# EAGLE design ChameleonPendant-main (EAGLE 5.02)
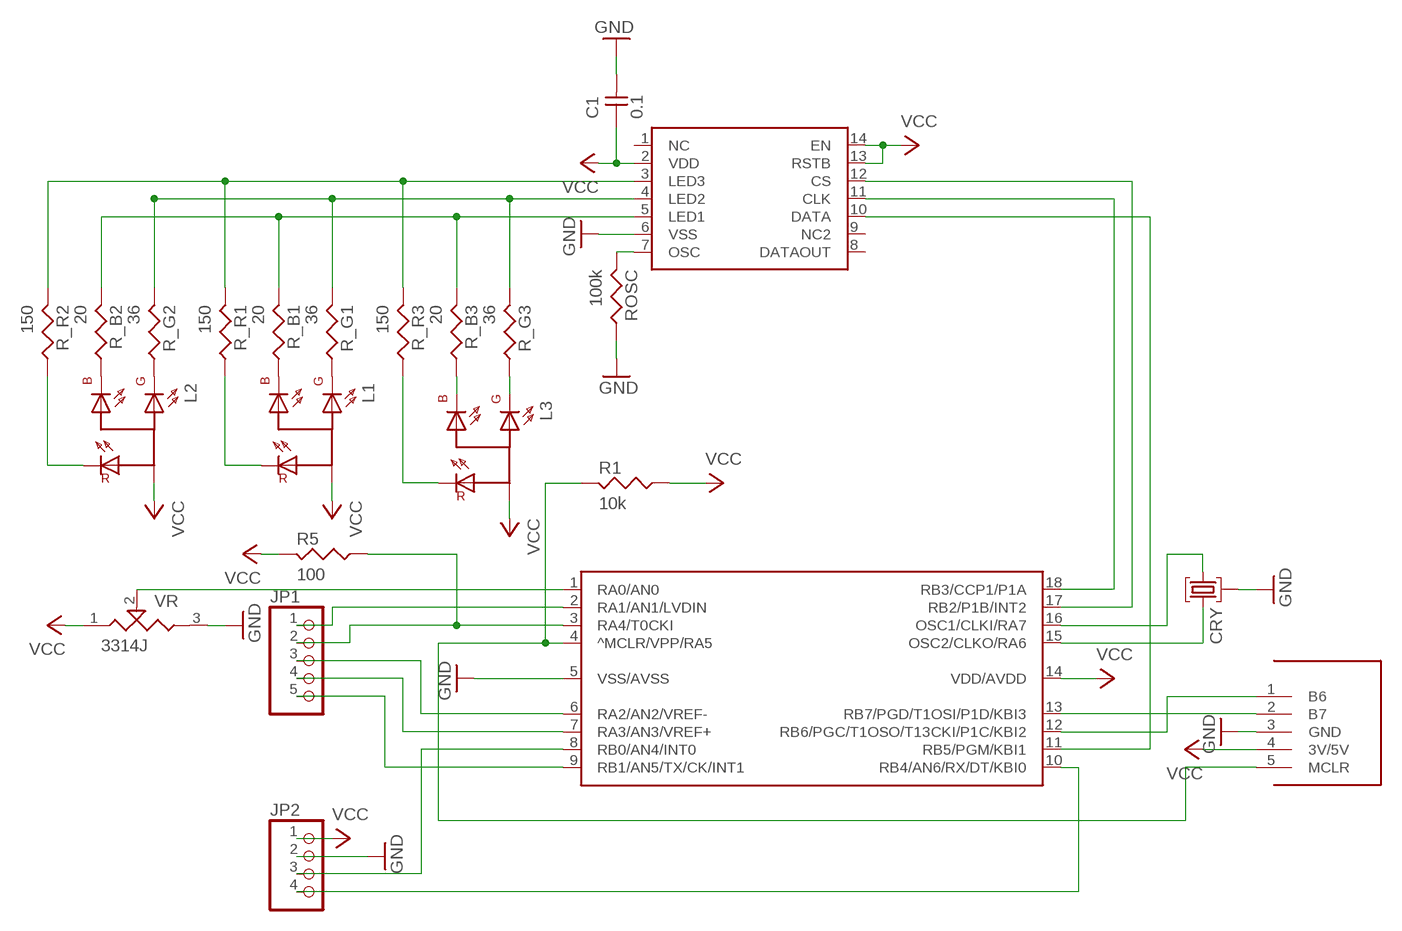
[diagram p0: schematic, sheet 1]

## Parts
C1  0.1  1608  [1608]
CRY  3-PIN-CRYSTALFLAT20M  [CRYSTAL-FLAT-20M]
JP1  PINHD-1X5DIP  [1X05]
JP2  PINHD-1X4DIP  [1X04]
L1  FULL_CHIPLED(LATBT66B)  [LATBT66B]
L2  FULL_CHIPLED(LATBT66B)  [LATBT66B]
L3  FULL_CHIPLED(LATBT66B)  [LATBT66B]
R1  10k  1608  [1608]
R5  100  1608  [1608]
R_B1  20  1608  [1608]
R_B2  20  1608  [1608]
R_B3  20  1608  [1608]
R_G1  36  1608  [1608]
R_G2  36  1608  [1608]
R_G3  36  1608  [1608]
R_R1  150  1608  [1608]
R_R2  150  1608  [1608]
R_R3  150  1608  [1608]
ROSC  100k  1608  [1608]
U$1  PIC18F1220SO  [SO-18W]
U$3  MODULAR-MINI08  [1.5MM-1X5S-8MM]
U$4  NJU6061  [SSOP14]
VR  3314J  [3314J]

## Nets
GND: C1.P$2 CRY.G(GND) JP2.2 ROSC.1 U$1.5(VSS/AVSS) U$3.3(GND) U$4.6(VSS) VR.3
N$1: R1.2 U$1.4(^MCLR/VPP/RA5) U$3.5(MCLR)
N$2: ROSC.2 U$4.7(OSC)
N$3: R_R1.2 R_R2.2 R_R3.2 U$4.3(LED3)
N$4: R_G1.2 R_G2.2 R_G3.2 U$4.4(LED2)
N$5: R_B1.2 R_B2.2 R_B3.2 U$4.5(LED1)
N$6: U$1.12(RB6/PGC/T1OSO/T13CKI/P1C/KBI2) U$3.1(B6)
N$7: L1.1(RED_C) R_R1.1
N$8: L3.1(RED_C) R_R3.1
N$9: L3.3(BLUE_C) R_B3.1
N$10: L3.4(GREEN_C) R_G3.1
N$11: L1.3(BLUE_C) R_B1.1
N$12: U$1.11(RB5/PGM/KBI1) U$4.10(DATA)
N$13: U$1.17(RB2/P1B/INT2) U$4.12(CS)
N$14: U$1.18(RB3/CCP1/P1A) U$4.11(CLK)
N$15: U$1.13(RB7/PGD/T1OSI/P1D/KBI3) U$3.2(B7)
N$16: CRY.O2 U$1.15(OSC2/CLKO/RA6)
N$17: CRY.O1 U$1.16(OSC1/CLKI/RA7)
N$18: U$1.1(RA0/AN0) VR.2
N$19: JP2.3 U$1.8(RB0/AN4/INT0)
N$20: L1.4(GREEN_C) R_G1.1
N$21: JP2.4 U$1.10(RB4/AN6/RX/DT/KBI0)
N$22: L2.1(RED_C) R_R2.1
N$23: L2.3(BLUE_C) R_B2.1
N$24: L2.4(GREEN_C) R_G2.1
N$25: JP1.1 U$1.2(RA1/AN1/LVDIN)
N$26: JP1.2 R5.1 U$1.3(RA4/T0CKI)
N$27: JP1.3 U$1.6(RA2/AN2/VREF-)
N$28: JP1.4 U$1.7(RA3/AN3/VREF+)
N$29: JP1.5 U$1.9(RB1/AN5/TX/CK/INT1)
VCC: C1.P$1 JP2.1 L1.2(A) L2.2(A) L3.2(A) R1.1 R5.2 U$1.14(VDD/AVDD) U$3.4(3V/5V) U$4.2(VDD) U$4.13(RSTB) U$4.14(EN) VR.1
Unconnected: U$4.1(NC) U$4.8(DATAOUT) U$4.9(NC2)

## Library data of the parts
C1 = 01_capacitor:1608
CRY = 00_other-parts:3-PIN-CRYSTAL: 3-pin crystal (center ground)
JP1 = 09_con-pin:PINHD-1X5: PIN HEADER
JP2 = 09_con-pin:PINHD-1X4: PIN HEADER
L1-L3 = 06_led:FULL_CHIPLED(LATBT66B)
R1 R5 R_B1-R_B3 R_G1-R_G3 R_R1-R_R3 ROSC = 02_resistor:1608
U$1 = 12_pic-micro:PIC18F1220
U$3 = 00_other-parts:MODULAR-MINI
U$4 = 10_other-ic:NJU6061
VR = 02_resistor:3314J

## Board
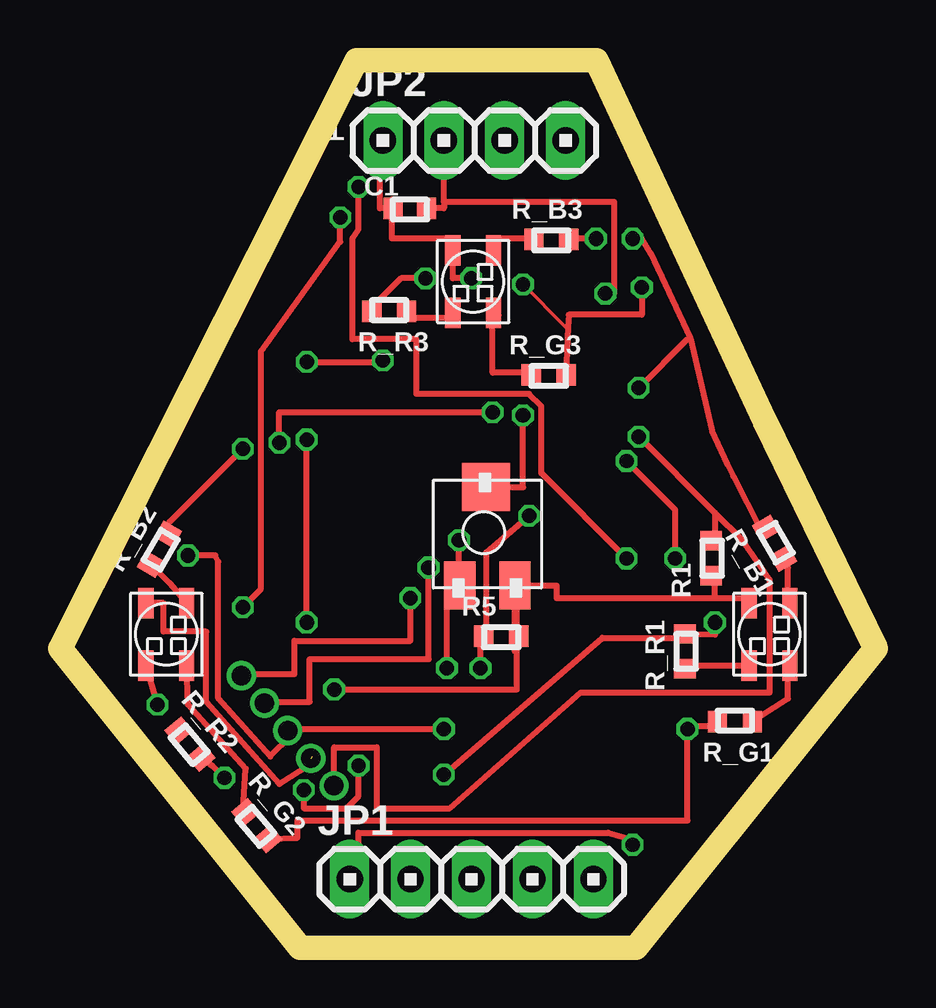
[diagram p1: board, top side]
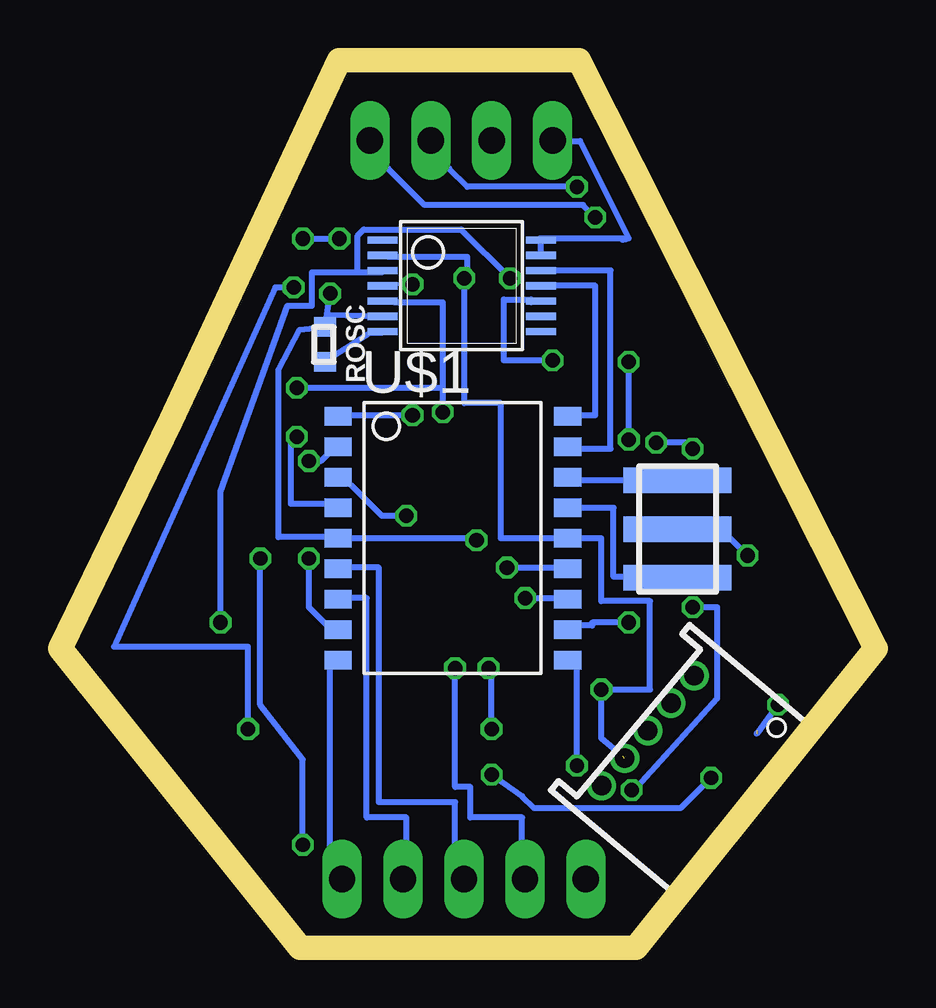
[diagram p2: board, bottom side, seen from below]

Size 34 x 37 mm. Coordinates in mm from the lower left corner, seen from the top.
Outline: 29.37,22 22.37,37 12.37,37 0,12.47 10,0 24,0 34,12.47 29.37,22
Copper layers (1*16): Top 0.035mm / dielectric 1.5mm / Bottom 0.035mm
Design rules "p-ban_min": minimum track width 0.15mm, minimum drill 0.3mm, track to track 0.15mm, track to pad 0.15mm, pad to pad 0.15mm, via to via 0.15mm, smd to smd 0.15mm, copper to edge 0.7mm, drill to drill 0.45mm, minimum pad ring 0.15mm, minimum via ring 0.15mm, stop-mask expansion 4mil, vias tented up to drill 0mil, thermal gap 0.15mm

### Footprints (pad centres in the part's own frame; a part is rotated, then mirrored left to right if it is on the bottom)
1608 = smd 0.8 x 0.9: P$1 -0.7,0.1; P$2 0.7,0.1
CRYSTAL-FLAT-20M = smd 1.067 x 4.5: G 0.027,0.016; O1 -2.019,0.016; O2 2.046,0.016
1X05 = drill 1.092 long: 1 -5.08,0; 2 -2.54,0; 3 0,0; 4 2.54,0; 5 5.08,0
1X04 = drill 1.092 long: 1 -3.81,0; 2 -1.27,0; 3 1.27,0; 4 3.81,0
LATBT66B = smd 0.635 x 1.27: 1 -0.85,-1.3; 2 -0.85,1.3; 3 0.85,1.3; 4 0.85,-1.3
1608' = smd 0.8 x 0.9: 1 -0.715,0.037; 2 0.739,0.037
SO-18W = smd 0.762 x 1.143: 1 -5.08,-4.788; 2 -3.81,-4.788; 3 -2.54,-4.788; 4 -1.27,-4.788; 5 0,-4.788; 6 1.27,-4.788; 7 2.54,-4.788; 8 3.81,-4.788; 9 5.08,-4.788; 10 5.08,4.788; 11 3.81,4.788; 12 2.54,4.788; 13 1.27,4.788; 14 0,4.788; 15 -1.27,4.788; 16 -2.54,4.788; 17 -3.81,4.788; 18 -5.08,4.788
1.5MM-1X5S-8MM = drill 0.813 round: 1 -3,-2; 2 -1.5,-2; 3 0,-2; 4 1.5,-2; 5 3,-2
SSOP14 = smd 0.305 x 1.245: 1 -1.587,-3.302; 2 -0.952,-3.302; 3 -0.317,-3.302; 4 0.318,-3.302; 5 0.953,-3.302; 6 1.588,-3.302; 7 2.223,-3.302; 8 2.223,3.302; 9 1.588,3.302; 10 0.953,3.302; 11 0.318,3.302; 12 -0.317,3.302; 13 -0.952,3.302; 14 -1.587,3.302
3314J = smd 1.3 x 2: 1 1.4,-2.4; 3 -0.9,-2.4 | smd 2 x 2: 2 0.2,1.7

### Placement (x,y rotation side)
C1  14.59,30.72 0 top
CRY  8.27,17.46 270 bottom
JP1  17.16,2.85 0 top
JP2  17.27,33.64 0 top
L1  29.58,13.06 0 top
L2  4.44,13.06 0 top
L3  17.22,27.76 0 top
R1  10k  [1608']  27.18,16.22 90 top
R5  100  [1608']  18.39,12.95 0 top
R_B1  20  [1608']  29.83,16.86 120 top
R_B2  20  [1608']  4.18,16.58 60 top
R_B3  20  [1608']  20.47,29.49 0 top
R_G1  36  [1608']  28.15,9.45 180 top
R_G2  36  [1608']  8.17,5.07 310 top
R_G3  36  [1608']  20.36,23.84 0 top
R_R1  150  [1608']  26.09,12.34 90 top
R_R2  150  [1608']  5.39,8.47 310 top
R_R3  150  [1608']  13.73,26.56 180 top
ROSC  100k  [1608']  22.99,25.16 270 bottom
U$1  17.62,17.06 270 bottom
U$3  7.96,7.75 230 bottom
U$4  17.25,27.9 270 bottom
VR  17.57,17.49 0 top

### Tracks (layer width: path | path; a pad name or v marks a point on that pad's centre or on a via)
GND  (via drill 0.61)
  Top 0.254: JP2.2 16,31.08 | C1.P$2 16,30.82 16,31.08 | v5.33,16.34 6.48,16.34 6.6,16.09 6.6,10.38 8.76,7.96 9.65,8.85 | 9.65,8.85 9.91,9.11 | 16.67,15.04 VR.3 | 16.67,15.04 16.76,14.95 16.64,14.95 | 16,31.08 23.11,31.08 23.11,27.27 v22.73,27.27 | 16.64,14.95 16.64,14.57 | 16.64,14.95 v16.64,16.98 | 16.67,15.04 16.13,15.04 v16.13,11.65 | 9.65,9.11 v16,9.11 | 9.65,8.85 9.65,9.11 | 9.4,9.11 9.4,9.04 U$3.3 | 9.65,9.11 9.4,9.11 | 9.4,9.11 9.4,9.23
  Bottom 0.254: 22.86,26.38 ROSC.1 24,25.76 24.89,24.09 24.89,17.11 22.35,17.11 22.35,17.06 U$1.5 16.64,17.06 v16.64,16.98 | 22.86,26.38 U$4.6 | 7.62,17.11 7.95,17.43 CRY.G 6.42,17.43 v5.33,16.34 | 22.86,26.38 v22.73,27.27 | v16.13,11.65 16,11.65 v16,9.11
N$1  (via drill 0.6)
  Top 0.254: 27.3,18.12 28.45,16.98 29.59,15.33 29.59,10.63 21.72,10.63 16.26,5.8 13.21,5.8 13.21,8.34 11.43,8.34 U$3.5 | 27.3,18.12 v24.13,21.3 | U$3.5 11.43,6.57 | U$3.5 | R1.2 27.3,16.96 27.3,18.12
  Bottom 0.15: v24.13,21.3 24.38,21.3 | 22.86,18.5 U$1.4
  Bottom 0.254: 22.86,18.5 24.38,18.5 24.38,21.3
N$2
  Bottom 0.254: ROSC.2 21.08,25.62 20.57,25.62 U$4.7
N$3  (via drill 0.6, 0.61)
  Top 0.15: 25.65,12.92 R_R1.2 | 13.21,26.89 R_R3.2
  Top 0.254: R_R1.2 27.3,13.04 v27.3,13.55 | v6.86,7.07 6.35,7.58 R_R2.2 | v16,7.2 22.61,12.92 25.65,12.92 | 13.21,26.89 14.22,27.9 v15.24,27.9
  Bottom 0.254: v27.3,13.55 27.3,19.01 24.51,26.76 23.5,26.76 23.5,28.16 21.59,28.16 | U$4.3 20.57,28.16 21.59,28.16 | v6.86,7.07 8.13,5.8 14.22,5.8 14.73,6.31 v16,7.2 | v15.24,27.9 17.27,29.93 21.34,29.93 21.59,29.68 21.59,28.16
N$4  (via drill 0.6, 0.61)
  Top 0.15: v19.3,27.65 21.08,25.87 21.18,25.87
  Top 0.254: R_G2.2 9.91,4.58 9.91,5.3 26.16,5.3 v26.16,9.11 26.16,9.23 27.43,9.23 27.43,9.35 | 27.43,9.35 27.43,9.36 | 27.43,9.35 R_G1.2 | v24.26,27.52 24.26,26.38 21.21,26.38 21.18,25.87 R_G3.2
  Bottom 0.15: v19.3,27.65 20.07,27.65 U$4.4
  Bottom 0.254: v26.16,9.11 26.16,12.54 31.75,12.54 25.02,27.52 v24.26,27.52
N$5  (via drill 0.6, 0.61)
  Top 0.15: R_B2.2 4.57,17.74 | 26.16,25.36 26.28,25.41
  Top 0.254: R_B1.2 29.21,17.4 28.07,19.65 27.81,20.15 27.18,21.55 26.28,25.41 24.64,28.92 24.26,29.55 v23.88,29.55 | 21.34,29.55 R_B3.2 | v22.35,29.55 21.34,29.55 | 21.34,29.55 21.34,29.43 | 4.57,17.74 v7.62,20.79 | v9.14,21.04 9.14,22.31 v18.03,22.31 | v24.13,23.33 26.16,25.36
  Bottom 0.15: v7.62,20.79 7.87,21.04 | 20.07,26.89 U$4.5
  Bottom 0.254: v23.88,29.55 v22.35,29.55 | 7.87,21.04 v9.14,21.04 | 18.03,23.33 18.03,26.89 20.07,26.89 | v18.03,22.31 18.03,23.33 | 18.03,23.33 v24.13,23.33
N$6  (via drill 0.61)
  Top 0.254: v14.61,14.57 14.61,12.79 9.78,12.79 9.78,11.4 7.62,11.4 7.62,11.34 U$3.1
  Bottom 0.254: U$1.12 12.83,14.44 | U$1.12 | v14.61,14.57 12.83,14.57 U$1.12
N$7
  Top 0.254: 26.04,11.61 26.04,11.52 | R_R1.1 26.04,11.61 | L1.1 26.04,11.76 26.04,11.61
N$8
  Top 0.254: L3.1 16.38,26.25 14.61,26.25 14.61,26.46 | 14.61,26.46 14.61,26.5 | R_R3.1 14.61,26.46
N$9
  Top 0.254: L3.3 18.03,29.06 18.03,29.55 19.81,29.55 19.81,29.59 R_B3.1
N$10
  Top 0.254: 18.29,26.35 18.03,26.46 L3.4 | 18.29,26.35 18.03,26.5 | 18.29,26.35 18.03,26.35 18.03,23.96 19.56,23.96 19.56,23.94 R_G3.1
N$11
  Top 0.254: R_B1.1 30.23,16.07 30.1,15.96 30.35,15.84 30.35,14.36 L1.3
N$12  (via drill 0.6, 0.61)
  Top 0.254: v10.29,13.55 v10.29,21.17 | v10.29,24.41 13.46,24.41 v13.46,24.47
  Bottom 0.254: v10.29,21.17 v10.29,24.41 | v10.29,13.55 11.81,13.55 11.81,13.42 12.95,13.42 12.95,13.25 U$1.11 | v13.46,24.47 15.49,24.47 15.49,27.01 14.35,27.01 14.35,26.95 | 14.35,26.95 14.35,26.89 | 14.35,26.95 U$4.10
N$13
  Bottom 0.254: U$4.12 11.05,28.22 11.05,20.79 12.57,20.79 12.57,20.87 U$1.17
N$14
  Bottom 0.254: U$4.11 11.68,27.58 11.68,22.19 13.08,22.19 13.08,22.14 U$1.18
N$15  (via drill 0.61)
  Top 0.254: 8.89,10.25 | 8.89,10.25 10.41,10.25 10.41,12.03 15.37,12.03 v15.37,15.84 | U$3.2 8.51,10.19 8.51,10.25 8.89,10.25
  Bottom 0.254: U$1.13 12.83,15.84 v15.37,15.84
N$16
  Bottom 0.254: U$1.15 10.92,18.33 10.92,15.46 8.13,15.46 8.13,15.41 | 8.13,15.41 8.13,15.33 | CRY.O2 8.13,15.41
N$17
  Bottom 0.254: 13.08,19.48 13.08,19.6 U$1.16 | CRY.O1 13.08,19.48 | 13.08,19.48 13.08,19.39
N$18  (via drill 0.61)
  Top 0.254: VR.2 19.3,19.19 v19.3,22.19
  Bottom 0.254: 22.48,22.14 22.48,22.06 | 22.48,22.14 U$1.1 | v19.3,22.19 22.48,22.19 22.48,22.14
N$19  (via drill 0.6)
  Top 0.254: v23.62,16.22 20.07,19.77 20.07,22.57 19.56,23.08 14.86,23.08 14.86,25.36 12.19,25.36 12.19,29.55 12.45,29.93 v12.45,31.71
  Bottom 0.15: U$1.8 22.86,13.42
  Bottom 0.254: 22.86,13.42 23.62,14.19 v23.62,16.22 | v12.45,31.71 17.02,31.71 17.78,32.47 JP2.3
N$20
  Top 0.254: L1.4 30.35,12.01 30.35,10.38 28.96,9.49 28.96,9.35 R_G1.1
N$21  (via drill 0.6)
  Top 0.254: v12.45,7.58 12.45,6.31 11.94,5.8 10.16,5.8 v10.16,6.57 | v7.62,14.19 8.38,14.95 8.38,24.85 11.68,29.43 v11.68,30.44
  Bottom 0.15: 10.16,6.44 v10.16,6.57 | 12.45,11.65 U$1.10
  Bottom 0.254: v12.45,7.58 12.45,11.65 | 10.16,6.44 6.6,10.38 6.6,14.19 v7.62,14.19 | v11.68,30.44 12.19,30.95 18.8,30.95 20.32,32.47 JP2.4
N$22  (via drill 0.6)  (1 unrouted)
  Top 0.254: v4.06,10.12 L2.1
  Bottom 0.254: v4.06,10.12 4.95,8.92
N$23
  Top 0.254: R_B2.1 4.57,15.2 L2.3
N$24
  Top 0.254: L2.4 5.33,10.12 7.75,7.46 7.62,5.42 R_G2.1
N$25  (via drill 0.6)
  Top 0.254: v23.62,20.28 25.65,18.25 v25.65,16.22 | v23.88,4.28 23.75,4.28 23.75,4.53 22.86,4.79 12.45,4.79 12.45,4.28 JP1.1
  Bottom 0.15: 22.86,20.54 U$1.2
  Bottom 0.254: 22.86,20.54 23.11,20.28 v23.62,20.28 | v25.65,16.22 25.65,10.12 23.88,7.84 v23.88,4.28
N$26  (via drill 0.6, 0.61)
  Top 0.15: R5.1 17.78,13.42
  Top 0.254: R5.1 17.53,13.05 v17.53,11.65 | v19.56,18 17.78,16.47 17.78,13.42
  Bottom 0.15: 21.84,19.27 U$1.3
  Bottom 0.254: JP1.2 14.73,2.85 14.73,5.42 16.89,5.42 16.89,6.69 17.53,6.69 v17.53,11.65 | 21.84,19.27 20.57,18 v19.56,18
N$27
  Bottom 0.254: JP1.3 17.53,2.85 17.53,6.06 20.7,6.06 20.7,15.84 22.35,15.84 22.35,15.79 U$1.6
N$28
  Bottom 0.254: JP1.4 19.56,2.85 19.56,5.42 21.21,5.42 21.21,14.57 22.23,14.57 | 22.23,14.57 22.23,14.52 U$1.7 | 22.23,14.57 22.23,14.69
N$29
  Bottom 0.254: 22.73,11.98 22.73,12.03 | 22.73,11.98 U$1.9 | JP1.5 22.73,2.85 22.73,11.98
VCC  (via drill 0.61)  (1 unrouted)
  Top 0.254: JP2.1 13.46,33.11 13.34,33.11 13.34,30.82 C1.P$1 13.84,31.2 13.84,29.55 16.26,29.55 16.26,29.17 | 16.26,29.06 16.26,28.92 | 16.26,29.06 L3.2 | 16.26,29.17 16.26,29.06 | R5.2 19.05,12.54 19.05,13.42 | VR.1 19.05,15.09 19.05,13.42 | VR.1 20.7,15.09 20.7,14.57 27.3,14.57 | L1.2 28.83,14.36 28.83,14.57 27.3,14.57 | L2.2 4.32,14.36 4.32,13.17 6.1,13.17 6.1,10.25 9.14,6.82 10.45,7.66 | 10.45,7.66 10.92,7.96 | VR.1 18.97,12.36 19.05,13.42 | 19.05,13.42 19.05,10.76 v11.43,10.76 | 16.26,29.17 16.38,29.17 16.38,27.9 v17.14,27.9 | 10.45,7.66 10.41,7.66 10.41,7.89 U$3.4 | R1.1 27.3,15.5 27.3,14.57
  Bottom 0.15: 10.67,7.84 10.73,7.9
  Bottom 0.254: 10.41,29.52 10.29,29.55 12.32,33.62 13.59,33.62 JP2.1 | 10.41,29.52 10.54,29.49 | 10.79,7.84 10.73,7.9 10.67,7.96 10.54,7.96 11.43,8.73 v11.43,10.76 9.4,10.76 9.4,14.44 11.43,14.44 11.43,17.06 U$1.14 15.62,17.06 15.62,22.7 17.14,22.7 v17.14,27.9 17.02,27.9 17.02,28.79 20.32,28.79 20.32,28.86 U$4.2 | 13.97,29.49 13.97,29.55 10.41,29.55 10.41,29.52 | 13.97,29.49 U$4.14 | U$4.13 13.97,28.86 13.97,29.49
